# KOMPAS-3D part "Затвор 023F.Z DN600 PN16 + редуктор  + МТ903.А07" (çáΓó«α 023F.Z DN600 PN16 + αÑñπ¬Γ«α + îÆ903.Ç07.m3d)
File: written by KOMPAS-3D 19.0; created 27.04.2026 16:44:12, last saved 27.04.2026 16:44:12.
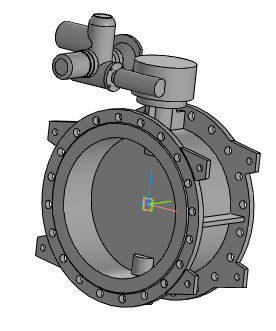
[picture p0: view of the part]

Document properties: Полное имя файла: ..\..\Затвор 023F.Z DN400-DN1600 + редуктор + МТ903\Затвор 023F.Z DN600 PN16 + редуктор + МТ903.А07.a3d

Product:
- Part/product: Затвор 023F.Z DN600 PN16 + редуктор  + МТ903.А07
    Масса: 541.728

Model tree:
1. Операция без истории:1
